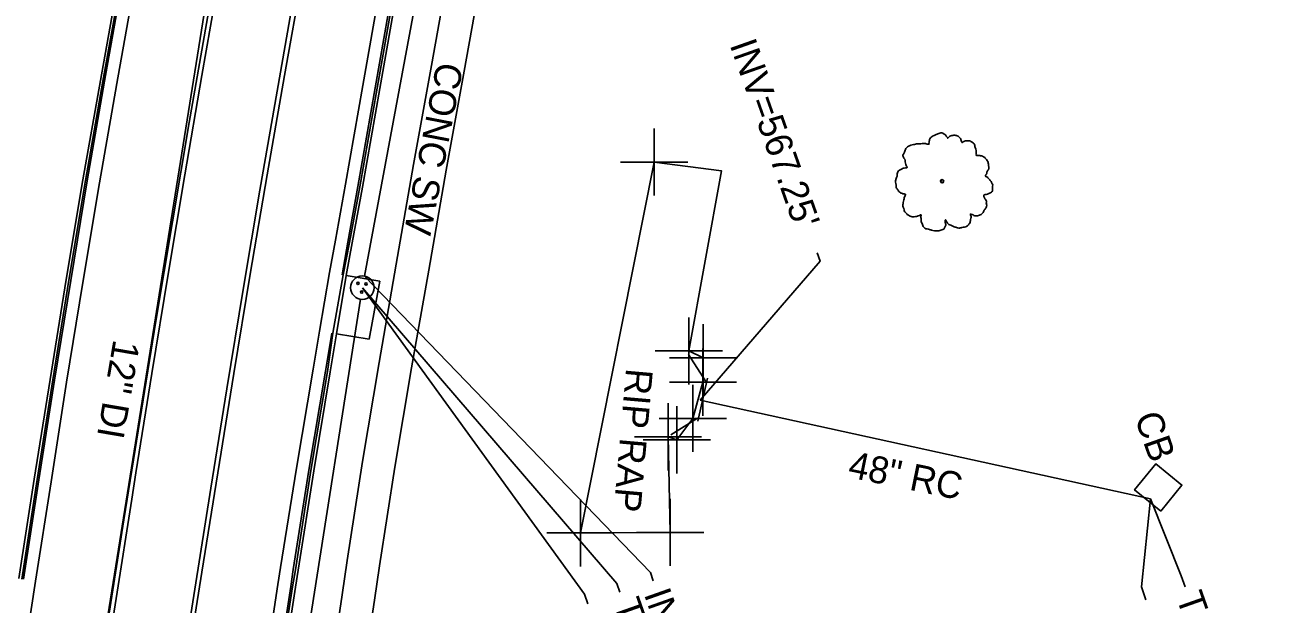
# Model space of a CAD drawing. Extents: x 2004847 to 2009016, y 1134161 to 1140101.
# Drawn here: x 2007553.9 to 2007739.4, y 1138089 to 1138175.3 of the extents above; entities that cross this region are included whole.
import ezdxf

# ---------------------------------------------------------------- set-up
doc = ezdxf.new("R2010")
doc.units = 0
for name, color, linetype in [('RD_EX_Bridge', 7, 'Continuous'), ('RD_EX_Conc', 7, 'Continuous'), ('RD_EX_Curb', 7, 'Continuous'), ('RD_EX_DR_Inlet', 7, 'Continuous'), ('RD_EX_DR_Inlet_txCode', 7, 'Continuous'), ('RD_EX_DR_Pipe', 7, 'Continuous'), ('RD_EX_DR_Pipe_txCode', 7, 'Continuous'), ('RD_EX_DV_Prop_txCode', 7, 'Continuous'), ('RD_EX_Misc', 7, 'Continuous'), ('RD_EX_Pavement_Markings', 7, 'Continuous'), ('RD_EX_Road', 7, 'Continuous'), ('RD_EX_UT', 7, 'Continuous'), ('RD_EX_VEG', 7, 'Continuous'), ('RD_Sketch2', 7, 'Continuous'), ('RD_Sketch3', 7, 'Continuous')]:
    doc.layers.add(name, color=color, linetype=linetype)

msp = doc.modelspace()

# ---------------------------------------------------------------- linework, layer by layer
at = {"layer": 'RD_EX_Bridge'}
for p, q in [((2007652.7, 1138126.13), (2007655.27, 1138122.14)), ((2007654.11, 1138116.2), (2007655.51, 1138122.64)), ((2007650.08, 1138114.18), (2007654.02, 1138116.67))]:
    msp.add_line(p, q, dxfattribs=at)
at = {"layer": 'RD_EX_Conc'}
for points in [[(2007628.22, 1138242.7), (2007625.4, 1138228.04), (2007622.58, 1138213.36), (2007619.71, 1138198.59), (2007617.06, 1138183.96), (2007614.44, 1138169.22), (2007611.75, 1138154.48), (2007609.19, 1138139.62), (2007606.66, 1138124.98), (2007604.16, 1138110.19), (2007601.88, 1138095.45), (2007601.14, 1138090.35)], [(2007633.09, 1138241.72), (2007630.28, 1138227.09), (2007627.46, 1138212.44), (2007624.55, 1138197.66), (2007621.91, 1138183.08), (2007619.29, 1138168.36), (2007616.61, 1138153.63), (2007614.02, 1138138.74), (2007611.47, 1138124.17), (2007608.98, 1138109.38), (2007606.7, 1138094.67), (2007605.96, 1138089.57)], [(2007586.61, 1138012.8), (2007590.48, 1138014.15), (2007592.21, 1138029.92), (2007594.33, 1138044.71), (2007596.47, 1138059.56), (2007598.75, 1138074.39), (2007601.14, 1138090.35)], [(2007597.39, 1137993.77), (2007595.76, 1137999.47), (2007593.95, 1138004.99), (2007594.96, 1138013.6), (2007597.06, 1138029.27), (2007599.17, 1138044.04), (2007601.28, 1138058.89), (2007603.54, 1138073.72), (2007605.96, 1138089.57)]]:
    msp.add_lwpolyline(points, dxfattribs=at)
at = {"layer": 'RD_EX_Curb'}
for points in [[(2007594.35, 1138314.79), (2007591.03, 1138300.07), (2007587.85, 1138285.31), (2007584.92, 1138271.01), (2007584.81, 1138270.56), (2007583.79, 1138265.47), (2007581.81, 1138255.83), (2007578.91, 1138241.01), (2007576.11, 1138226.25), (2007573.33, 1138211.43), (2007570.55, 1138196.61), (2007567.78, 1138181.78), (2007565.13, 1138166.97), (2007562.52, 1138152.16), (2007560.03, 1138137.31), (2007557.65, 1138122.45), (2007555.27, 1138107.6), (2007552.98, 1138092.77)], [(2007594.75, 1138314.7), (2007591.43, 1138299.98), (2007588.24, 1138285.23), (2007585.21, 1138270.48), (2007582.23, 1138255.74), (2007579.3, 1138240.93), (2007576.5, 1138226.17), (2007573.72, 1138211.35), (2007570.94, 1138196.54), (2007568.17, 1138181.71), (2007565.52, 1138166.9), (2007562.91, 1138152.1), (2007560.44, 1138137.24), (2007558.03, 1138122.39), (2007555.73, 1138107.52), (2007553.43, 1138092.7)], [(2007594.98, 1138314.65), (2007591.67, 1138299.93), (2007588.46, 1138285.18), (2007585.48, 1138270.42), (2007582.48, 1138255.69), (2007579.55, 1138240.88), (2007576.72, 1138226.13), (2007573.94, 1138211.31), (2007571.16, 1138196.5), (2007568.39, 1138181.67), (2007565.74, 1138166.86), (2007563.16, 1138152.05), (2007560.71, 1138137.19), (2007558.29, 1138122.35), (2007555.98, 1138107.48), (2007553.67, 1138092.66)], [(2007620.85, 1138244.2), (2007620, 1138239.3), (2007617.22, 1138224.6), (2007614.4, 1138209.92), (2007611.56, 1138195.25), (2007608.94, 1138180.56), (2007606.33, 1138165.85), (2007603.75, 1138151.14), (2007602.21, 1138142.85), (2007601.3, 1138138.01), (2007599.72, 1138129.32), (2007598.95, 1138123.64), (2007596.47, 1138108.88), (2007594.16, 1138094.07), (2007593.75, 1138091.54)], [(2007621.37, 1138244.09), (2007620.44, 1138239.21), (2007617.65, 1138224.52), (2007614.83, 1138209.83), (2007611.99, 1138195.17), (2007609.32, 1138180.49), (2007606.72, 1138165.78), (2007604.14, 1138151.07), (2007602.63, 1138142.78), (2007601.74, 1138137.93), (2007600.28, 1138129.23), (2007599.33, 1138123.58), (2007596.9, 1138108.81), (2007594.57, 1138094.01), (2007594.17, 1138091.47)], [(2007620.67, 1138244.23), (2007619.77, 1138239.34), (2007616.95, 1138224.66), (2007614.14, 1138209.97), (2007611.27, 1138195.31), (2007608.65, 1138180.62), (2007606.04, 1138165.9), (2007603.46, 1138151.19), (2007601.97, 1138142.89), (2007601.11, 1138138.04)], [(2007599.58, 1138129.34), (2007598.66, 1138123.69), (2007596.16, 1138108.93), (2007593.85, 1138094.12), (2007593.49, 1138091.58)], [(2007585.25, 1138015.75), (2007584.79, 1138017.7), (2007584.6, 1138019.13), (2007584.25, 1138021.11), (2007584.17, 1138023.11), (2007584.16, 1138025.11), (2007584.3, 1138027.12), (2007584.36, 1138028.58), (2007584.61, 1138030.56), (2007586.69, 1138045.4), (2007588.81, 1138060.25), (2007590.97, 1138075.09), (2007593.49, 1138091.58)], [(2007585.42, 1138015.79), (2007584.99, 1138017.74), (2007584.75, 1138019.13), (2007584.5, 1138021.12), (2007584.42, 1138023.12), (2007584.41, 1138025.12), (2007584.45, 1138027.13), (2007584.56, 1138028.55), (2007584.78, 1138030.54), (2007586.8, 1138045.39), (2007588.99, 1138060.23), (2007591.23, 1138075.06), (2007593.75, 1138091.54)], [(2007585.87, 1138015.89), (2007585.43, 1138017.84), (2007585.22, 1138019.15), (2007584.96, 1138021.14), (2007584.88, 1138023.14), (2007584.85, 1138025.14), (2007584.96, 1138027.15), (2007585.04, 1138028.49), (2007585.24, 1138030.48), (2007587.3, 1138045.32), (2007589.48, 1138060.16), (2007591.67, 1138075), (2007594.17, 1138091.47)]]:
    msp.add_lwpolyline(points, dxfattribs=at)
at = {"layer": 'RD_EX_DR_Inlet'}
for p, q in [((2007606.72, 1138137.1), (2007601.74, 1138137.93)), ((2007723.01, 1138102.82), (2007726.16, 1138106.71))]:
    msp.add_line(p, q, dxfattribs=at)
msp.add_lwpolyline([(2007600.28, 1138129.23), (2007605.13, 1138128.44), (2007606.72, 1138137.1)], dxfattribs=at)
msp.add_lwpolyline([(2007723.01, 1138102.82), (2007726.16, 1138106.71), (2007722.27, 1138109.85), (2007719.12, 1138105.97)], close=True, dxfattribs=at)
for centre, radius in [((2007604.14, 1138136.11), 1.75), ((2007603.47, 1138136.74), 0.175), ((2007604.7, 1138136.67), 0.175), ((2007604.05, 1138135.45), 0.175)]:
    msp.add_circle(centre, radius, dxfattribs=at)
at = {"layer": 'RD_EX_DR_Inlet_txCode'}
for points in [[(2007654.46, 1138119.36), (2007672.31, 1138140.04), (2007671.87, 1138141.29)], [(2007604.46, 1138137.83), (2007647.02, 1138093.69), (2007647.46, 1138092.45)], [(2007604.14, 1138136.11), (2007642.01, 1138092.04), (2007642.47, 1138090.75)], [(2007604.14, 1138136.11), (2007637.22, 1138090.46), (2007637.73, 1138089.01)], [(2007721.5, 1138104.66), (2007720.14, 1138091.53), (2007720.82, 1138089.59)], [(2007721.5, 1138104.66), (2007726.06, 1138093.16), (2007726.64, 1138091.52)]]:
    msp.add_lwpolyline(points, dxfattribs=at)
at = {"layer": 'RD_EX_DR_Pipe'}
for p, q in [((2007625.16, 1138249.11), (2007604.46, 1138137.83)), ((2007603.86, 1138134.38), (2007585.16, 1138015.45)), ((2007721.5, 1138104.66), (2007654.46, 1138119.36))]:
    msp.add_line(p, q, dxfattribs=at)
at = {"layer": 'RD_EX_DV_Prop_txCode'}
for p, q in [((2007647.58, 1138149.82), (2007647.58, 1138159.82)), ((2007642.58, 1138154.82), (2007652.58, 1138154.82)), ((2007652.75, 1138121.68), (2007652.75, 1138131.68)), ((2007654.88, 1138120.65), (2007654.88, 1138130.65)), ((2007647.75, 1138126.68), (2007657.75, 1138126.68)), ((2007654.86, 1138117.03), (2007654.86, 1138127.03)), ((2007649.88, 1138125.65), (2007659.88, 1138125.65)), ((2007649.86, 1138122.03), (2007659.86, 1138122.03)), ((2007653.35, 1138111.64), (2007653.35, 1138121.64)), ((2007649.65, 1138108.88), (2007649.65, 1138118.88)), ((2007650.96, 1138108.44), (2007650.96, 1138118.44)), ((2007648.35, 1138116.64), (2007658.35, 1138116.64)), ((2007644.65, 1138113.88), (2007654.65, 1138113.88)), ((2007645.96, 1138113.44), (2007655.96, 1138113.44)), ((2007636.62, 1138094.56), (2007636.62, 1138104.56)), ((2007649.97, 1138094.65), (2007649.97, 1138104.65)), ((2007631.62, 1138099.56), (2007641.62, 1138099.56)), ((2007644.97, 1138099.65), (2007654.97, 1138099.65))]:
    msp.add_line(p, q, dxfattribs=at)
at = {"layer": 'RD_EX_Misc'}
msp.add_lwpolyline([(2007652.75, 1138126.68), (2007654.88, 1138125.65), (2007654.86, 1138122.03), (2007653.35, 1138116.64), (2007650.96, 1138113.44), (2007649.65, 1138113.88), (2007649.97, 1138099.65), (2007636.62, 1138099.56), (2007647.58, 1138154.82), (2007657.61, 1138153.53), (2007652.75, 1138126.68)], dxfattribs=at)
at = {"layer": 'RD_EX_Pavement_Markings'}
for points in [[(2007624.02, 1138381.2), (2007620.51, 1138366.4), (2007617.08, 1138351.8), (2007613.72, 1138337.18), (2007610.39, 1138322.55), (2007607.1, 1138307.92), (2007603.9, 1138293.26), (2007600.8, 1138278.59), (2007597.76, 1138263.9), (2007594.77, 1138249.2), (2007591.88, 1138234.48), (2007589.01, 1138219.76), (2007586.23, 1138205.02), (2007583.53, 1138190.26), (2007580.92, 1138175.49), (2007578.37, 1138160.71), (2007575.85, 1138145.92), (2007573.39, 1138131.13), (2007570.99, 1138116.32), (2007568.63, 1138101.51), (2007566.28, 1138086.69)], [(2007570.41, 1138108.52), (2007572.8, 1138123.33), (2007575.24, 1138138.13), (2007577.7, 1138152.93), (2007580.25, 1138167.71), (2007582.82, 1138182.48), (2007585.45, 1138197.25), (2007588.23, 1138211.99), (2007591.03, 1138226.73), (2007593.92, 1138241.45), (2007596.89, 1138256.15), (2007599.89, 1138270.85), (2007602.99, 1138285.52), (2007606.12, 1138300.19), (2007609.35, 1138314.84), (2007612.65, 1138329.47), (2007615.98, 1138344.1), (2007619.41, 1138358.7), (2007622.86, 1138373.3), (2007624.37, 1138379.7)], [(2007581.57, 1138106.22), (2007583.97, 1138121.03), (2007586.4, 1138135.83), (2007588.86, 1138150.63), (2007591.43, 1138165.4), (2007594.03, 1138180.18), (2007596.75, 1138194.93), (2007599.54, 1138209.67), (2007602.33, 1138224.41), (2007605.21, 1138239.13), (2007608.19, 1138253.83), (2007611.18, 1138268.53), (2007614.26, 1138283.21), (2007617.36, 1138297.88), (2007620.55, 1138312.54), (2007623.77, 1138327.19), (2007627.02, 1138341.83), (2007630.4, 1138356.45), (2007633.76, 1138371.07), (2007635.6, 1138379.12)], [(2007635.19, 1138373.48), (2007631.6, 1138358.72), (2007628.24, 1138344.1), (2007624.98, 1138329.46), (2007621.76, 1138314.81), (2007618.58, 1138300.15), (2007615.42, 1138285.49), (2007612.35, 1138270.81), (2007609.31, 1138256.12), (2007606.37, 1138241.41), (2007603.48, 1138226.69), (2007600.64, 1138211.96), (2007597.86, 1138197.22), (2007595.16, 1138182.47), (2007592.53, 1138167.7), (2007589.96, 1138152.92), (2007587.45, 1138138.13), (2007585.02, 1138123.33), (2007582.62, 1138108.52), (2007580.24, 1138093.71)], [(2007558.63, 1138030.43), (2007560.8, 1138045.28), (2007562.96, 1138060.12), (2007565.15, 1138074.96), (2007567.46, 1138089.78), (2007569.8, 1138104.6), (2007570.41, 1138108.52)], [(2007581.57, 1138106.22), (2007579.19, 1138091.2), (2007576.86, 1138076.38), (2007574.55, 1138061.56), (2007572.4, 1138046.71), (2007570.33, 1138031.85)], [(2007567.09, 1138001), (2007568.98, 1138015.88), (2007570.88, 1138030.76), (2007572.91, 1138045.62), (2007575.05, 1138060.47), (2007577.32, 1138075.29), (2007580.24, 1138093.71)]]:
    msp.add_lwpolyline(points, dxfattribs=at)
at = {"layer": 'RD_EX_Road'}
for points in [[(2007596.79, 1138314.24), (2007593.54, 1138299.52), (2007590.34, 1138284.78), (2007587.3, 1138270.05), (2007584.28, 1138255.33), (2007581.37, 1138240.53), (2007578.55, 1138225.77), (2007575.78, 1138210.97), (2007573, 1138196.16), (2007570.23, 1138181.35), (2007567.58, 1138166.54), (2007565, 1138151.74), (2007562.51, 1138136.9), (2007560.11, 1138122.05), (2007557.78, 1138107.2), (2007555.48, 1138092.37)], [(2007618.91, 1138244.58), (2007617.92, 1138239.71), (2007615.07, 1138225.03), (2007612.29, 1138210.32), (2007609.45, 1138195.65), (2007606.8, 1138180.95), (2007604.19, 1138166.23), (2007601.61, 1138151.51), (2007600.16, 1138143.19), (2007599.27, 1138138.35), (2007597.78, 1138129.64), (2007596.83, 1138123.99), (2007594.34, 1138109.22), (2007591.97, 1138094.42), (2007591.56, 1138091.89)], [(2007506.49, 1137990.71), (2007512.07, 1137992.01), (2007516.63, 1137993.86), (2007520.97, 1137996.01), (2007525.15, 1137998.57), (2007528.97, 1138001.52), (2007532.5, 1138004.74), (2007535.78, 1138008.51), (2007538.63, 1138012.41), (2007541.03, 1138016.59), (2007543.1, 1138020.99), (2007544.8, 1138025.5), (2007545.96, 1138030.36), (2007546.83, 1138035.18), (2007547.63, 1138040.11), (2007549.89, 1138054.93), (2007552.08, 1138069.77), (2007554.3, 1138084.6), (2007555.48, 1138092.37)], [(2007589.05, 1138075.36), (2007591.56, 1138091.89)]]:
    msp.add_lwpolyline(points, dxfattribs=at)
at = {"layer": 'RD_EX_UT'}
msp.add_line((2007536.83, 1137903.27), (2007600.86, 1138303.84), dxfattribs=at)
at = {"layer": 'RD_EX_VEG'}
for centre, radius in [((2007690.45, 1138151.97), 0.25), ((2007690.44, 1138151.95), 0.0001)]:
    msp.add_circle(centre, radius, dxfattribs=at)
for points in [[(2007690.58, 1138159.14), (2007690.28, 1138159.17), (2007689.96, 1138159.07), (2007689.71, 1138158.97), (2007689.48, 1138158.89), (2007689.26, 1138158.79), (2007688.96, 1138158.62), (2007688.73, 1138158.42), (2007688.61, 1138158.17), (2007688.56, 1138157.94), (2007688.51, 1138157.67), (2007688.51, 1138157.49), (2007688.38, 1138157.47), (2007688.23, 1138157.49), (2007687.98, 1138157.57), (2007687.73, 1138157.57), (2007687.48, 1138157.57), (2007687.13, 1138157.54), (2007686.78, 1138157.54), (2007686.51, 1138157.49), (2007686.18, 1138157.44), (2007685.81, 1138157.32), (2007685.46, 1138157.19), (2007685.16, 1138156.94), (2007684.91, 1138156.47), (2007684.78, 1138156.12), (2007684.63, 1138155.87), (2007684.78, 1138155.42), (2007684.96, 1138155.07), (2007684.98, 1138154.87), (2007685.06, 1138154.44), (2007685.16, 1138154.22), (2007685.28, 1138154.02), (2007685.21, 1138153.99), (2007684.83, 1138153.94), (2007684.53, 1138153.84), (2007684.11, 1138153.62), (2007683.88, 1138153.39), (2007683.78, 1138153.07), (2007683.76, 1138152.72), (2007683.66, 1138152.52), (2007683.58, 1138152.24), (2007683.56, 1138152.17), (2007683.51, 1138151.84), (2007683.61, 1138151.39), (2007683.63, 1138151.04), (2007683.76, 1138150.82), (2007683.91, 1138150.64), (2007684.08, 1138150.39), (2007684.48, 1138150.17), (2007684.81, 1138150.07), (2007685.01, 1138150.04), (2007684.83, 1138149.54), (2007684.78, 1138149.19), (2007684.66, 1138148.79), (2007684.66, 1138148.72), (2007684.61, 1138148.25), (2007684.76, 1138147.92), (2007684.83, 1138147.55), (2007685.01, 1138147.32), (2007685.28, 1138147.02), (2007685.61, 1138146.8), (2007686.11, 1138146.67), (2007686.51, 1138146.7), (2007687.08, 1138146.87), (2007687.33, 1138146.95), (2007687.31, 1138146.77), (2007687.33, 1138146.4), (2007687.33, 1138145.97), (2007687.48, 1138145.65), (2007687.58, 1138145.37), (2007687.73, 1138145.12), (2007688.06, 1138144.9), (2007688.46, 1138144.82), (2007688.88, 1138144.67), (2007689.33, 1138144.6), (2007689.83, 1138144.57), (2007690.43, 1138144.72), (2007690.71, 1138144.85), (2007690.81, 1138145.02), (2007691.01, 1138145.4), (2007690.96, 1138145.62), (2007690.98, 1138146.22), (2007691.08, 1138146.05), (2007691.26, 1138145.7), (2007691.76, 1138145.4), (2007692.16, 1138145.22), (2007692.63, 1138145.07), (2007692.93, 1138145), (2007693.4, 1138145.07), (2007693.78, 1138145.15), (2007694.15, 1138145.27), (2007694.45, 1138145.55), (2007694.63, 1138145.82), (2007694.68, 1138146.1), (2007694.75, 1138146.47), (2007694.8, 1138146.65)], [(2007694.8, 1138146.65), (2007694.73, 1138146.82), (2007694.68, 1138147.07), (2007694.75, 1138147.05), (2007694.93, 1138147), (2007695.2, 1138146.87), (2007695.43, 1138146.8), (2007695.75, 1138146.82), (2007696.03, 1138146.92), (2007696.48, 1138147.2), (2007696.75, 1138147.67), (2007697.03, 1138148.07), (2007697.1, 1138148.39), (2007697.05, 1138148.62), (2007697.03, 1138149.12), (2007696.83, 1138149.37), (2007696.78, 1138149.49), (2007696.68, 1138149.89), (2007696.75, 1138149.94), (2007697.03, 1138149.99), (2007697.4, 1138150.12), (2007697.68, 1138150.24), (2007697.9, 1138150.42), (2007697.98, 1138150.64), (2007697.95, 1138151.04), (2007698, 1138151.44), (2007697.93, 1138151.59), (2007697.83, 1138151.74), (2007697.75, 1138151.94), (2007697.6, 1138152.09), (2007697.5, 1138152.24), (2007697.4, 1138152.34), (2007697.28, 1138152.49), (2007697.1, 1138152.62), (2007696.95, 1138152.67), (2007696.9, 1138152.82), (2007697.05, 1138153.02), (2007697.1, 1138153.12), (2007697.13, 1138153.34), (2007697.35, 1138153.69), (2007697.4, 1138154.09), (2007697.35, 1138154.52), (2007697.3, 1138154.79), (2007697.15, 1138155.07), (2007696.95, 1138155.32), (2007696.83, 1138155.49), (2007696.65, 1138155.62), (2007696.33, 1138155.74), (2007696.08, 1138155.79), (2007695.73, 1138155.79), (2007695.53, 1138155.84), (2007695.55, 1138155.89), (2007695.55, 1138156.04), (2007695.55, 1138156.32), (2007695.48, 1138156.77), (2007695.33, 1138157.27), (2007695.33, 1138157.29), (2007695.23, 1138157.54), (2007695, 1138157.74), (2007694.83, 1138157.84), (2007694.63, 1138157.97), (2007694.38, 1138157.99), (2007694.08, 1138157.99), (2007693.8, 1138157.94), (2007693.6, 1138157.84), (2007693.43, 1138157.72), (2007693.35, 1138157.87), (2007693.25, 1138158.17), (2007693.2, 1138158.32), (2007693.05, 1138158.49), (2007692.83, 1138158.69), (2007692.38, 1138158.82), (2007691.76, 1138158.74), (2007691.46, 1138158.54), (2007691.31, 1138158.37), (2007691.26, 1138158.49), (2007691.06, 1138158.69), (2007690.96, 1138158.87), (2007690.78, 1138158.99), (2007690.63, 1138159.09), (2007690.53, 1138159.14)]]:
    msp.add_spline(points, degree=3, dxfattribs=at)

# ---------------------------------------------------------------- texts
at = {"layer": 'RD_EX_DR_Inlet_txCode'}
for s, p in [("INV=567.25'", (2007658.8, 1138172.31)), ('CB', (2007719.07, 1138116.83)), ("INV=570.03'", (2007646.03, 1138090.47)), ("TOP=578.72'", (2007725.27, 1138090.02)), ("TOP=575.58'", (2007641.48, 1138089.02))]:
    msp.add_text(s, height=4, rotation=289.4494, dxfattribs=at).set_placement(p)
at = {"layer": 'RD_EX_DR_Pipe_txCode'}
msp.add_text('48" RC', height=4, rotation=348.4217, dxfattribs=at).set_placement((2007676.29, 1138107.9))
at = {"layer": 'RD_Sketch2'}
msp.add_text('12" DI', height=4, rotation=260.3108, dxfattribs=at).set_placement((2007567.09, 1138128.5))
at = {"layer": 'RD_Sketch3'}
for s, rotation, p in [('CONC SW', 259.0235, (2007615.26, 1138169.89)), ('RIP RAP', 265.0139, (2007643.42, 1138124.18))]:
    msp.add_text(s, height=4, rotation=rotation, dxfattribs=at).set_placement(p)

doc.saveas('drawing.dxf')
